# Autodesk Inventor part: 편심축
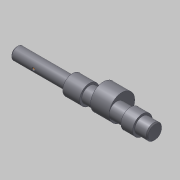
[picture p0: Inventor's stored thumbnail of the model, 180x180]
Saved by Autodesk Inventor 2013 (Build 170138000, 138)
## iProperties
Company: 한국ATC센터
Created: 2015-12
Part Number: 편심축
Document SubType Name: Modeling
Designer: mdu
Density: 7.86 g/cm^3
Mass: 225.292 g
Surface Area: 81.2409 cm^2
Volume: 28.6631 cm^3
Material: 강철, 연강
Author: mdu
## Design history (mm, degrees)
sketch "스케치1"
  geometry: L1 (-86, 0)-(86, 0); L2 (-86, 0)-(-86, 6); L3 (-86, 6)-(-32, 6); L4 (-32, 6)-(-32, 9.5); L5 (-32, 9.5)-(-15.5, 9.5); L6 (-15.5, 9.5)-(-15.5, 7.5); L7 (-15.5, 7.5)-(48, 7.5); L8 (86, 6)-(86, 0); L9 (36, 7.5)-(36, 9.5); L10 (36, 9.5)-(24.5, 9.5); L11 (24.5, 9.5)-(24.5, 7.5); L12 (48, 7.5)-(48, 6); L13 (48, 6)-(86, 6); 2 further points
  constraints: 26 end point, 6 parallel, 6 perpendicular, 2 point on line, 1 coincident, 1 horizontal, 1 midpoint
  dimensions: "d1" = 12 diameter of L3 L1; "d2" = 15 diameter of L7 L1; "d4" = 16.5 distance of L4.end L5.end; "d5" = 19 diameter of L5 L1; "d24" = 11.5 distance of L9.end L10.end; "d25" = 19 diameter of L10 L1; "d27" = 40 distance between parallel lines of L11 L6; "d28" = 54 distance of L2.end L3.end; "d29" = 50 distance between parallel lines of L8 L9; "d41" = 38 distance between parallel lines of L8 L12; "d42" = 12 diameter of L13 L1
revolve "회전1" stored, may be unused: angle "d6" = 90 deg
node "작업 평면1"
sketch "스케치2"
  geometry: C1 r 7.5 at (0, 0) reference; C2 r 12.5 at (0, 5); 1 further point
  constraints: 1 centre point, 1 tangent, 1 vertical alignment
  dimensions: "d9" = 25 diameter of C2
extrude "돌출1" join sketch "스케치2" distance "d10" = 18; taper "d11" = 0 deg
chamfer "모따기1" distance "d12" = 1; stored, may be unused: second distance "d13" = 2, angle "d14" = 45 deg
node "작업 평면2"
sketch "스케치3"
  geometry: L1 (7, -2)-(21, -2); L2 (21, 2)-(7, 2); L3 (27, 5)-(27, -5) reference; A1 r 2 centre (21, 0) between (21, -2) and (21, 2); A2 r 2 centre (7, 0) between (7, 2) and (7, -2); 2 further points
  constraints: 4 end point, 4 point on circle, 4 tangent, 2 centre point, 1 horizontal, 1 horizontal alignment, 1 midpoint, 1 parallel
  dimensions: "d18" = 4 distance edge to line of A1 L3; "d19" = 4 distance between parallel lines of L2 L1; "d20" = 18 dimension on A1 A2
extrude "돌출2" cut sketch "스케치3" distance "d21" = 2.5; taper "d22" = 0 deg
revolve "회전2" stored, may be unused: angle "d26" = 90 deg
node "작업 평면3"
sketch "스케치4"
  geometry: L1 (44, 5)-(44, -5) reference; 2 further points
  constraints: 1 horizontal alignment
  dimensions: "d30" = 12 distance from line of point (32, 0) L1
hole "구멍1" sketch "스케치4" at (32, 0) diameter "d31" = 6; stored, may be unused: countersink angle "d35" = 90 deg, drill point angle "d37" = 118 deg; dims "d32" = 6, "d33" = 14, "d34" = 3, "d36" = 8
node "작업 평면4"
sketch "스케치5"
  geometry: C1 r 3 at (32, 0) reference; C2 r 8 at (32, 0); 2 further points
  constraints: 1 centre point, 1 coincident, 1 other
  dimensions: "d38" = 16 diameter of C2
extrude "돌출3" cut sketch "스케치5" distance "d39" = 3; taper "d40" = 0 deg
sketch "스케치6"
  geometry: L1 (-85, -6)-(-32, -6) reference; L2 (-86, -5)-(-86, 5) reference; L3 (-85, 6)-(-32, 6) reference; L4 (-64, 6)-(-64, -6); L5 (-64, -6)-(-62.5, -6); L6 (-64, -4.5)-(-62.5, -6); L7 (-64, -6)-(-64, -4.5); 2 further points
  constraints: 8 end point, 4 point on line, 2 perpendicular, 1 coincident
  dimensions: "d43" = 22 distance between parallel lines of L4 L2; "d44" = 45 deg angle of L6 L7; "d45" = 3 diameter of L5.end L4
revolve "회전3" stored, may be unused: angle "d46" = 90 deg
node "작업점1"
chamfer "모따기3" distance "d47" = 0.5; stored, may be unused: second distance "d48" = 2, angle "d49" = 45 deg
sketch "스케치7"
  geometry: C1 r 7.5 at (0, 0) reference; 1 further point
extrude "돌출4" cut sketch "스케치7" stored distance "d50" = 10; taper "d51" = 0 deg
chamfer "모따기4" distance "d52" = 1; stored, may be unused: second distance "d53" = 2, angle "d54" = 45 deg
node "작업 평면6"
node "솔리드1"
node "투영된 루프1"
other parameters: "d7" = 8.5
